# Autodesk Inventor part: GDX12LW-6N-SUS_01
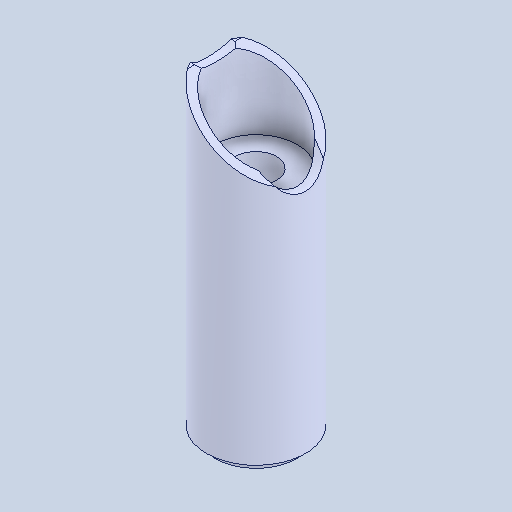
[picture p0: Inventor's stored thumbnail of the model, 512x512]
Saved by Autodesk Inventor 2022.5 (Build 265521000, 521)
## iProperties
Created: 2024-06
Part Number: GDX12LW-6N-SUS_01
Material: 一般
Document SubType Name: Modeling
Designer: ImaoCorp
Density: 1 g/cm^3
Appearance: 既定
Author: ImaoCorp
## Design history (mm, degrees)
feature "GDX12LW-6N-SUS_01"
node "ソリッド1"
